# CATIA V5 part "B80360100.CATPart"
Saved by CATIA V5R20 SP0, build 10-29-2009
Part number: B80360100
Revision: 3
Definition: design
Nomenclature: B80360100
Source: made
Description: NOT SPECIFIED
Bounding box of the stored display mesh (mm): x -42.5 to 42.5, y -42.5 to 42.5, z 0 to 100
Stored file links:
  C:\Users\Utente\Desktop\3D files B803\B80360100.CATPart
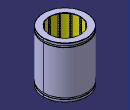
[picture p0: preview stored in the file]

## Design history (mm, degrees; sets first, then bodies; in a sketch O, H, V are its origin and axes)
Body1 "MANIFOLD_SOLID_BREP #38" (main body)
  Solid1: solid without history
Body2 "MANIFOLD_SOLID_BREP #76"
  Solid2: solid without history
Body3 "MANIFOLD_SOLID_BREP #114"
  Solid3: solid without history
Body4 "MANIFOLD_SOLID_BREP #152"
  Solid4: solid without history
Body5 "MANIFOLD_SOLID_BREP #190"
  Solid5: solid without history
Body6 "MANIFOLD_SOLID_BREP #228"
  Solid6: solid without history
Body7 "MANIFOLD_SOLID_BREP #266"
  Solid7: solid without history
Body8 "MANIFOLD_SOLID_BREP #304"
  Solid8: solid without history
Body9 "MANIFOLD_SOLID_BREP #3200"
  Solid9: solid without history
Body10 "MANIFOLD_SOLID_BREP #3238"
  Solid10: solid without history
Body11 "MANIFOLD_SOLID_BREP #3276"
  Solid11: solid without history
Body12 "MANIFOLD_SOLID_BREP #3314"
  Solid12: solid without history
Body13 "MANIFOLD_SOLID_BREP #3352"
  Solid13: solid without history
Body14 "MANIFOLD_SOLID_BREP #3390"
  Solid14: solid without history
Body15 "MANIFOLD_SOLID_BREP #3428"
  Solid15: solid without history
Body16 "MANIFOLD_SOLID_BREP #3466"
  Solid16: solid without history
Body17 "MANIFOLD_SOLID_BREP #3504"
  Solid17: solid without history
Body18 "MANIFOLD_SOLID_BREP #3542"
  Solid18: solid without history
Body19 "MANIFOLD_SOLID_BREP #3580"
  Solid19: solid without history
Body20 "MANIFOLD_SOLID_BREP #3618"
  Solid20: solid without history
Body21 "MANIFOLD_SOLID_BREP #3656"
  Solid21: solid without history
Body22 "MANIFOLD_SOLID_BREP #3694"
  Solid22: solid without history
Body23 "MANIFOLD_SOLID_BREP #3732"
  Solid23: solid without history
Body24 "MANIFOLD_SOLID_BREP #3770"
  Solid24: solid without history
Body25 "MANIFOLD_SOLID_BREP #3808"
  Solid25: solid without history
Body26 "MANIFOLD_SOLID_BREP #3846"
  Solid26: solid without history
Body27 "MANIFOLD_SOLID_BREP #3884"
  Solid27: solid without history
Body28 "MANIFOLD_SOLID_BREP #3922"
  Solid28: solid without history
Body29 "MANIFOLD_SOLID_BREP #3960"
  Solid29: solid without history
Body30 "MANIFOLD_SOLID_BREP #3998"
  Solid30: solid without history
Body31 "MANIFOLD_SOLID_BREP #4036"
  Solid31: solid without history
Body32 "MANIFOLD_SOLID_BREP #4074"
  Solid32: solid without history
Body33 "MANIFOLD_SOLID_BREP #4112"
  Solid33: solid without history
Body34 "MANIFOLD_SOLID_BREP #4150"
  Solid34: solid without history
Body35 "MANIFOLD_SOLID_BREP #4188"
  Solid35: solid without history
Body36 "MANIFOLD_SOLID_BREP #4226"
  Solid36: solid without history
Body37 "MANIFOLD_SOLID_BREP #4264"
  Solid37: solid without history
Body38 "MANIFOLD_SOLID_BREP #4302"
  Solid38: solid without history
Body39 "MANIFOLD_SOLID_BREP #4340"
  Solid39: solid without history
Body40 "MANIFOLD_SOLID_BREP #4378"
  Solid40: solid without history
Body41 "MANIFOLD_SOLID_BREP #4416"
  Solid41: solid without history
Body42 "MANIFOLD_SOLID_BREP #4454"
  Solid42: solid without history
Body43 "MANIFOLD_SOLID_BREP #4492"
  Solid43: solid without history
Body44 "MANIFOLD_SOLID_BREP #4530"
  Solid44: solid without history
Body45 "MANIFOLD_SOLID_BREP #4568"
  Solid45: solid without history
Body46 "MANIFOLD_SOLID_BREP #4606"
  Solid46: solid without history
Body47 "MANIFOLD_SOLID_BREP #4644"
  Solid47: solid without history
Body48 "MANIFOLD_SOLID_BREP #4682"
  Solid48: solid without history
Body49 "MANIFOLD_SOLID_BREP #4720"
  Solid49: solid without history
Body50 "MANIFOLD_SOLID_BREP #4758"
  Solid50: solid without history
Body51 "MANIFOLD_SOLID_BREP #4796"
  Solid51: solid without history
Body52 "MANIFOLD_SOLID_BREP #4834"
  Solid52: solid without history
Body53 "MANIFOLD_SOLID_BREP #4872"
  Solid53: solid without history
Body54 "MANIFOLD_SOLID_BREP #4910"
  Solid54: solid without history
Body55 "MANIFOLD_SOLID_BREP #4948"
  Solid55: solid without history
Body56 "MANIFOLD_SOLID_BREP #4986"
  Solid56: solid without history
Body57 "MANIFOLD_SOLID_BREP #5024"
  Solid57: solid without history
Body58 "MANIFOLD_SOLID_BREP #5062"
  Solid58: solid without history
Body59 "MANIFOLD_SOLID_BREP #5100"
  Solid59: solid without history
Body60 "MANIFOLD_SOLID_BREP #5138"
  Solid60: solid without history
Body61 "MANIFOLD_SOLID_BREP #5176"
  Solid61: solid without history
Body62 "MANIFOLD_SOLID_BREP #5214"
  Solid62: solid without history
Body63 "MANIFOLD_SOLID_BREP #5252"
  Solid63: solid without history
Body64 "MANIFOLD_SOLID_BREP #5290"
  Solid64: solid without history
Body65 "MANIFOLD_SOLID_BREP #5328"
  Solid65: solid without history
Body66 "MANIFOLD_SOLID_BREP #5366"
  Solid66: solid without history
Body67 "MANIFOLD_SOLID_BREP #5404"
  Solid67: solid without history
Body68 "MANIFOLD_SOLID_BREP #5442"
  Solid68: solid without history
Body69 "MANIFOLD_SOLID_BREP #5480"
  Solid69: solid without history
Body70 "MANIFOLD_SOLID_BREP #5518"
  Solid70: solid without history
Body71 "MANIFOLD_SOLID_BREP #5556"
  Solid71: solid without history
Body72 "MANIFOLD_SOLID_BREP #5594"
  Solid72: solid without history
Body73 "MANIFOLD_SOLID_BREP #5632"
  Solid73: solid without history
Body74 "MANIFOLD_SOLID_BREP #5670"
  Solid74: solid without history
Body75 "MANIFOLD_SOLID_BREP #5708"
  Solid75: solid without history
Body76 "MANIFOLD_SOLID_BREP #5746"
  Solid76: solid without history
Body77 "MANIFOLD_SOLID_BREP #5784"
  Solid77: solid without history
Body78 "MANIFOLD_SOLID_BREP #5822"
  Solid78: solid without history
Body79 "MANIFOLD_SOLID_BREP #5860"
  Solid79: solid without history
Body80 "MANIFOLD_SOLID_BREP #5898"
  Solid80: solid without history
Body81 "MANIFOLD_SOLID_BREP #5936"
  Solid81: solid without history
Body82 "MANIFOLD_SOLID_BREP #5974"
  Solid82: solid without history
Body83 "MANIFOLD_SOLID_BREP #6012"
  Solid83: solid without history
Body84 "MANIFOLD_SOLID_BREP #6050"
  Solid84: solid without history
Body85 "MANIFOLD_SOLID_BREP #6088"
  Solid85: solid without history
Body86 "MANIFOLD_SOLID_BREP #6126"
  Solid86: solid without history
Body87 "MANIFOLD_SOLID_BREP #6164"
  Solid87: solid without history
Body88 "MANIFOLD_SOLID_BREP #6202"
  Solid88: solid without history
Body89 "MANIFOLD_SOLID_BREP #6240"
  Solid89: solid without history
Body90 "MANIFOLD_SOLID_BREP #6278"
  Solid90: solid without history
Body91 "MANIFOLD_SOLID_BREP #6316"
  Solid91: solid without history
Body92 "MANIFOLD_SOLID_BREP #6354"
  Solid92: solid without history
Body93 "MANIFOLD_SOLID_BREP #6392"
  Solid93: solid without history
Body94 "MANIFOLD_SOLID_BREP #6430"
  Solid94: solid without history
Body95 "MANIFOLD_SOLID_BREP #6468"
  Solid95: solid without history
Body96 "MANIFOLD_SOLID_BREP #6506"
  Solid96: solid without history
Body97 "MANIFOLD_SOLID_BREP #6544"
  Solid97: solid without history
Body98 "MANIFOLD_SOLID_BREP #6582"
  Solid98: solid without history
Body99 "MANIFOLD_SOLID_BREP #6620"
  Solid99: solid without history
Body100 "MANIFOLD_SOLID_BREP #6658"
  Solid100: solid without history
Body101 "MANIFOLD_SOLID_BREP #6696"
  Solid101: solid without history
Body102 "MANIFOLD_SOLID_BREP #6734"
  Solid102: solid without history
Body103 "MANIFOLD_SOLID_BREP #6772"
  Solid103: solid without history
Body104 "MANIFOLD_SOLID_BREP #6810"
  Solid104: solid without history
Body105 "MANIFOLD_SOLID_BREP #6848"
  Solid105: solid without history
Body106 "MANIFOLD_SOLID_BREP #6886"
  Solid106: solid without history
Body107 "MANIFOLD_SOLID_BREP #6924"
  Solid107: solid without history
Body108 "MANIFOLD_SOLID_BREP #6962"
  Solid108: solid without history
Body109 "MANIFOLD_SOLID_BREP #7000"
  Solid109: solid without history
Body110 "MANIFOLD_SOLID_BREP #7038"
  Solid110: solid without history
Body111 "MANIFOLD_SOLID_BREP #7076"
  Solid111: solid without history
Body112 "MANIFOLD_SOLID_BREP #7114"
  Solid112: solid without history
Body113 "MANIFOLD_SOLID_BREP #7152"
  Solid113: solid without history
Body114 "MANIFOLD_SOLID_BREP #7190"
  Solid114: solid without history
Body115 "MANIFOLD_SOLID_BREP #7228"
  Solid115: solid without history
Body116 "MANIFOLD_SOLID_BREP #7266"
  Solid116: solid without history
Body117 "MANIFOLD_SOLID_BREP #7304"
  Solid117: solid without history
Body118 "MANIFOLD_SOLID_BREP #7342"
  Solid118: solid without history
Body119 "MANIFOLD_SOLID_BREP #7380"
  Solid119: solid without history
Body120 "MANIFOLD_SOLID_BREP #7418"
  Solid120: solid without history
Body121 "MANIFOLD_SOLID_BREP #7456"
  Solid121: solid without history
Body122 "MANIFOLD_SOLID_BREP #7494"
  Solid122: solid without history
Body123 "MANIFOLD_SOLID_BREP #7532"
  Solid123: solid without history
Body124 "MANIFOLD_SOLID_BREP #7570"
  Solid124: solid without history
Body125 "MANIFOLD_SOLID_BREP #7608"
  Solid125: solid without history
Body126 "MANIFOLD_SOLID_BREP #7646"
  Solid126: solid without history
Body127 "MANIFOLD_SOLID_BREP #7684"
  Solid127: solid without history
Body128 "MANIFOLD_SOLID_BREP #7722"
  Solid128: solid without history
Body129 "MANIFOLD_SOLID_BREP #7760"
  Solid129: solid without history
Body130 "MANIFOLD_SOLID_BREP #7798"
  Solid130: solid without history
Body131 "MANIFOLD_SOLID_BREP #7836"
  Solid131: solid without history
Body132 "MANIFOLD_SOLID_BREP #7874"
  Solid132: solid without history
Body133 "MANIFOLD_SOLID_BREP #7912"
  Solid133: solid without history
Body134 "MANIFOLD_SOLID_BREP #7950"
  Solid134: solid without history
Body135 "MANIFOLD_SOLID_BREP #7988"
  Solid135: solid without history
Body136 "MANIFOLD_SOLID_BREP #8026"
  Solid136: solid without history
Body137 "MANIFOLD_SOLID_BREP #8064"
  Solid137: solid without history
Body138 "MANIFOLD_SOLID_BREP #8102"
  Solid138: solid without history
Body139 "MANIFOLD_SOLID_BREP #8140"
  Solid139: solid without history
Body140 "MANIFOLD_SOLID_BREP #8178"
  Solid140: solid without history
Body141 "MANIFOLD_SOLID_BREP #8216"
  Solid141: solid without history
Body142 "MANIFOLD_SOLID_BREP #8254"
  Solid142: solid without history
Body143 "MANIFOLD_SOLID_BREP #8292"
  Solid143: solid without history
Body144 "MANIFOLD_SOLID_BREP #8330"
  Solid144: solid without history
Body145 "MANIFOLD_SOLID_BREP #8368"
  Solid145: solid without history
Body146 "MANIFOLD_SOLID_BREP #8406"
  Solid146: solid without history
Body147 "MANIFOLD_SOLID_BREP #8444"
  Solid147: solid without history
Body148 "MANIFOLD_SOLID_BREP #8482"
  Solid148: solid without history
Body149 "MANIFOLD_SOLID_BREP #8520"
  Solid149: solid without history
Body150 "MANIFOLD_SOLID_BREP #8558"
  Solid150: solid without history
Body151 "MANIFOLD_SOLID_BREP #8596"
  Solid151: solid without history
Body152 "MANIFOLD_SOLID_BREP #8634"
  Solid152: solid without history
Body153 "MANIFOLD_SOLID_BREP #8672"
  Solid153: solid without history
Body154 "MANIFOLD_SOLID_BREP #8710"
  Solid154: solid without history
Body155 "MANIFOLD_SOLID_BREP #8748"
  Solid155: solid without history
Body156 "MANIFOLD_SOLID_BREP #8786"
  Solid156: solid without history
Body157 "MANIFOLD_SOLID_BREP #8824"
  Solid157: solid without history
Body158 "MANIFOLD_SOLID_BREP #8862"
  Solid158: solid without history
Body159 "MANIFOLD_SOLID_BREP #8900"
  Solid159: solid without history
Body160 "MANIFOLD_SOLID_BREP #8938"
  Solid160: solid without history
Body161 "MANIFOLD_SOLID_BREP #8976"
  Solid161: solid without history
Body162 "MANIFOLD_SOLID_BREP #9014"
  Solid162: solid without history
Body163 "MANIFOLD_SOLID_BREP #9052"
  Solid163: solid without history
Body164 "MANIFOLD_SOLID_BREP #9090"
  Solid164: solid without history
Body165 "MANIFOLD_SOLID_BREP #9128"
  Solid165: solid without history
Body166 "MANIFOLD_SOLID_BREP #9166"
  Solid166: solid without history
Body167 "MANIFOLD_SOLID_BREP #9204"
  Solid167: solid without history
Body168 "MANIFOLD_SOLID_BREP #9242"
  Solid168: solid without history
Body169 "MANIFOLD_SOLID_BREP #9280"
  Solid169: solid without history
Body170 "MANIFOLD_SOLID_BREP #9318"
  Solid170: solid without history
Body171 "MANIFOLD_SOLID_BREP #9356"
  Solid171: solid without history
Body172 "MANIFOLD_SOLID_BREP #9394"
  Solid172: solid without history
Body173 "MANIFOLD_SOLID_BREP #9432"
  Solid173: solid without history
Body174 "MANIFOLD_SOLID_BREP #9470"
  Solid174: solid without history
Body175 "MANIFOLD_SOLID_BREP #9508"
  Solid175: solid without history
Body176 "MANIFOLD_SOLID_BREP #9546"
  Solid176: solid without history
Body177 "MANIFOLD_SOLID_BREP #9584"
  Solid177: solid without history
Body178 "MANIFOLD_SOLID_BREP #9622"
  Solid178: solid without history
Body179 "MANIFOLD_SOLID_BREP #9660"
  Solid179: solid without history
Body180 "MANIFOLD_SOLID_BREP #9698"
  Solid180: solid without history
Body181 "MANIFOLD_SOLID_BREP #9736"
  Solid181: solid without history
Body182 "MANIFOLD_SOLID_BREP #9774"
  Solid182: solid without history
Body183 "MANIFOLD_SOLID_BREP #9812"
  Solid183: solid without history
Body184 "MANIFOLD_SOLID_BREP #9850"
  Solid184: solid without history
Body185 "MANIFOLD_SOLID_BREP #9888"
  Solid185: solid without history
Body186 "MANIFOLD_SOLID_BREP #9926"
  Solid186: solid without history
Body187 "MANIFOLD_SOLID_BREP #9964"
  Solid187: solid without history
Body188 "MANIFOLD_SOLID_BREP #10002"
  Solid188: solid without history
Body189 "MANIFOLD_SOLID_BREP #10040"
  Solid189: solid without history
Body190 "MANIFOLD_SOLID_BREP #10078"
  Solid190: solid without history
Body191 "MANIFOLD_SOLID_BREP #10116"
  Solid191: solid without history
Body192 "MANIFOLD_SOLID_BREP #10154"
  Solid192: solid without history
Body193 "MANIFOLD_SOLID_BREP #10192"
  Solid193: solid without history
Body194 "MANIFOLD_SOLID_BREP #10230"
  Solid194: solid without history
Body195 "MANIFOLD_SOLID_BREP #10268"
  Solid195: solid without history
Body196 "MANIFOLD_SOLID_BREP #10306"
  Solid196: solid without history
Body197 "MANIFOLD_SOLID_BREP #10344"
  Solid197: solid without history
Body198 "MANIFOLD_SOLID_BREP #10382"
  Solid198: solid without history
Body199 "MANIFOLD_SOLID_BREP #10420"
  Solid199: solid without history
Body200 "MANIFOLD_SOLID_BREP #10458"
  Solid200: solid without history
Body201 "MANIFOLD_SOLID_BREP #10496"
  Solid201: solid without history
Body202 "MANIFOLD_SOLID_BREP #10534"
  Solid202: solid without history
Body203 "MANIFOLD_SOLID_BREP #10572"
  Solid203: solid without history
Body204 "MANIFOLD_SOLID_BREP #10610"
  Solid204: solid without history
Body205 "MANIFOLD_SOLID_BREP #10648"
  Solid205: solid without history
Body206 "MANIFOLD_SOLID_BREP #10686"
  Solid206: solid without history
Body207 "MANIFOLD_SOLID_BREP #10724"
  Solid207: solid without history
Body208 "MANIFOLD_SOLID_BREP #10762"
  Solid208: solid without history
Body209 "MANIFOLD_SOLID_BREP #10800"
  Solid209: solid without history
Body210 "MANIFOLD_SOLID_BREP #10838"
  Solid210: solid without history
Body211 "MANIFOLD_SOLID_BREP #10876"
  Solid211: solid without history
Body212 "MANIFOLD_SOLID_BREP #10914"
  Solid212: solid without history
Body213 "MANIFOLD_SOLID_BREP #10952"
  Solid213: solid without history
Body214 "MANIFOLD_SOLID_BREP #10990"
  Solid214: solid without history
Body215 "MANIFOLD_SOLID_BREP #11028"
  Solid215: solid without history
Body216 "MANIFOLD_SOLID_BREP #11066"
  Solid216: solid without history
Body217 "MANIFOLD_SOLID_BREP #11104"
  Solid217: solid without history
Body218 "MANIFOLD_SOLID_BREP #11142"
  Solid218: solid without history
Body219 "MANIFOLD_SOLID_BREP #11180"
  Solid219: solid without history
Body220 "MANIFOLD_SOLID_BREP #11218"
  Solid220: solid without history
Body221 "MANIFOLD_SOLID_BREP #11256"
  Solid221: solid without history
Body222 "MANIFOLD_SOLID_BREP #11294"
  Solid222: solid without history
Body223 "MANIFOLD_SOLID_BREP #11332"
  Solid223: solid without history
Body224 "MANIFOLD_SOLID_BREP #11370"
  Solid224: solid without history
Body225 "MANIFOLD_SOLID_BREP #11408"
  Solid225: solid without history
Body226 "MANIFOLD_SOLID_BREP #11446"
  Solid226: solid without history
Body227 "MANIFOLD_SOLID_BREP #11484"
  Solid227: solid without history
Body228 "MANIFOLD_SOLID_BREP #11522"
  Solid228: solid without history
Body229 "MANIFOLD_SOLID_BREP #11560"
  Solid229: solid without history
Body230 "MANIFOLD_SOLID_BREP #11598"
  Solid230: solid without history
Body231 "MANIFOLD_SOLID_BREP #11636"
  Solid231: solid without history
Body232 "MANIFOLD_SOLID_BREP #11674"
  Solid232: solid without history
Body233 "MANIFOLD_SOLID_BREP #11712"
  Solid233: solid without history
Body234 "MANIFOLD_SOLID_BREP #11750"
  Solid234: solid without history
Body235 "MANIFOLD_SOLID_BREP #11788"
  Solid235: solid without history
Body236 "MANIFOLD_SOLID_BREP #11826"
  Solid236: solid without history
Body237 "MANIFOLD_SOLID_BREP #11864"
  Solid237: solid without history
Body238 "MANIFOLD_SOLID_BREP #11902"
  Solid238: solid without history
Body239 "MANIFOLD_SOLID_BREP #11940"
  Solid239: solid without history
Body240 "MANIFOLD_SOLID_BREP #11978"
  Solid240: solid without history
Body241 "MANIFOLD_SOLID_BREP #12016"
  Solid241: solid without history
Body242 "MANIFOLD_SOLID_BREP #12054"
  Solid242: solid without history
Body243 "MANIFOLD_SOLID_BREP #12092"
  Solid243: solid without history
Body244 "MANIFOLD_SOLID_BREP #12130"
  Solid244: solid without history
Body245 "MANIFOLD_SOLID_BREP #12168"
  Solid245: solid without history
Body246 "MANIFOLD_SOLID_BREP #12206"
  Solid246: solid without history
Body247 "MANIFOLD_SOLID_BREP #12244"
  Solid247: solid without history
Body248 "MANIFOLD_SOLID_BREP #12282"
  Solid248: solid without history
Body249 "MANIFOLD_SOLID_BREP #12320"
  Solid249: solid without history
Body250 "MANIFOLD_SOLID_BREP #12358"
  Solid250: solid without history
Body251 "MANIFOLD_SOLID_BREP #12396"
  Solid251: solid without history
Body252 "MANIFOLD_SOLID_BREP #12434"
  Solid252: solid without history
Body253 "MANIFOLD_SOLID_BREP #12472"
  Solid253: solid without history
Body254 "MANIFOLD_SOLID_BREP #12510"
  Solid254: solid without history
Body255 "MANIFOLD_SOLID_BREP #12548"
  Solid255: solid without history
Body256 "MANIFOLD_SOLID_BREP #12586"
  Solid256: solid without history
Body257 "MANIFOLD_SOLID_BREP #12624"
  Solid257: solid without history
Body258 "MANIFOLD_SOLID_BREP #12662"
  Solid258: solid without history
Body259 "MANIFOLD_SOLID_BREP #12700"
  Solid259: solid without history
Body260 "MANIFOLD_SOLID_BREP #12738"
  Solid260: solid without history
Body261 "MANIFOLD_SOLID_BREP #12776"
  Solid261: solid without history
Body262 "MANIFOLD_SOLID_BREP #12814"
  Solid262: solid without history
Body263 "MANIFOLD_SOLID_BREP #12852"
  Solid263: solid without history
Body264 "MANIFOLD_SOLID_BREP #12890"
  Solid264: solid without history
Body265 "MANIFOLD_SOLID_BREP #12928"
  Solid265: solid without history
Body266 "MANIFOLD_SOLID_BREP #12966"
  Solid266: solid without history
Body267 "MANIFOLD_SOLID_BREP #13004"
  Solid267: solid without history
Body268 "MANIFOLD_SOLID_BREP #13042"
  Solid268: solid without history
Body269 "MANIFOLD_SOLID_BREP #13080"
  Solid269: solid without history
Body270 "MANIFOLD_SOLID_BREP #13118"
  Solid270: solid without history
Body271 "MANIFOLD_SOLID_BREP #13156"
  Solid271: solid without history
Body272 "MANIFOLD_SOLID_BREP #13194"
  Solid272: solid without history
Body273 "MANIFOLD_SOLID_BREP #13232"
  Solid273: solid without history
Body274 "MANIFOLD_SOLID_BREP #13270"
  Solid274: solid without history
Body275 "MANIFOLD_SOLID_BREP #13308"
  Solid275: solid without history
Body276 "MANIFOLD_SOLID_BREP #13346"
  Solid276: solid without history
Body277 "MANIFOLD_SOLID_BREP #13384"
  Solid277: solid without history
